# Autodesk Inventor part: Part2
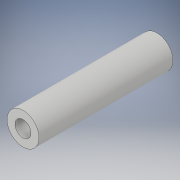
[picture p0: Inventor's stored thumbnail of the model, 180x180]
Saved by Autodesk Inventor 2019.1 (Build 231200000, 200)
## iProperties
Created: 2018-09
Part Number: Part2
Material: Generic
Document SubType Name: Modeling
Designer: drawing
Density: 1 g/cm^3
Appearance: Default
Author: drawing
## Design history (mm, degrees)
sketch "Sketch1"
  geometry: C1 r 3.175 at (0, 0); C2 r 1.587 at (0, 0); 1 further point
  constraints: 2 centre point, 2 coincident
  dimensions: "d0" = 6.35 diameter of C1; "d1" = 3.175 diameter of C2
extrude "Extrusion1" new body sketch "Sketch1" stored distance "d2" = 26.67; taper "d3" = 0 deg
body "Solid1"
